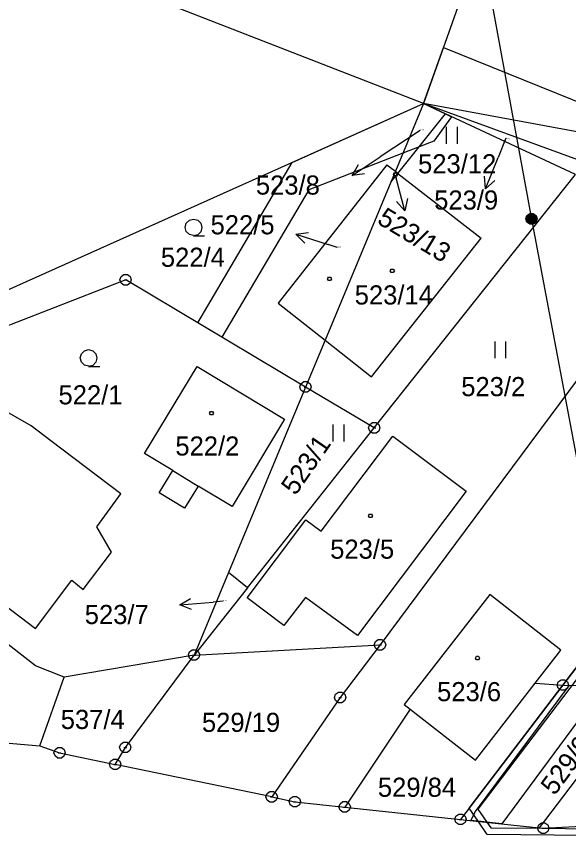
# Model space of a CAD drawing. Extents: x -759060 to -757386, y -1172273 to -1170948.
# Drawn here: x -758613.1 to -758564, y -1171852.3 to -1171779.5 of the extents above; entities that cross this region are included whole.
import ezdxf

# ---------------------------------------------------------------- set-up
doc = ezdxf.new("R2010")
doc.units = 0
for name, color, linetype in [('Vrstva 1', 7, 'Continuous'), ('Vrstva 12', 7, 'Continuous'), ('Vrstva 13', 7, 'Continuous'), ('Vrstva 2', 7, 'Continuous'), ('Vrstva 3', 7, 'Continuous'), ('Vrstva 4', 7, 'Continuous'), ('Vrstva 5', 7, 'Continuous'), ('Vrstva 6', 7, 'Continuous'), ('Vrstva 7', 7, 'Continuous'), ('Vrstva 8', 7, 'Continuous')]:
    doc.layers.add(name, color=color, linetype=linetype)

msp = doc.modelspace()

# ---------------------------------------------------------------- linework, layer by layer
at = {"layer": 'Vrstva 1'}
for p, q in [((-758552.98, -1171720.14), (-758576.87, -1171787.26)), ((-758576.87, -1171787.26), (-758612.62, -1171773.32)), ((-758616.41, -1171804.96), (-758576.87, -1171787.26)), ((-758576.87, -1171787.26), (-758579.37, -1171793.28)), ((-758574.91, -1171788.18), (-758576.87, -1171787.26)), ((-758550.98, -1171792.01), (-758576.87, -1171787.26)), ((-758562.5, -1171792.5), (-758576.87, -1171787.26)), ((-758579.14, -1171793.46), (-758574.91, -1171788.18)), ((-758563.35, -1171793.57), (-758574.91, -1171788.18)), ((-758580.12, -1171792.7), (-758589.8, -1171804.99)), ((-758580.12, -1171792.7), (-758579.37, -1171793.28)), ((-758581.24, -1171816.1), (-758563.35, -1171793.57)), ((-758579.37, -1171793.28), (-758579.77, -1171794.24)), ((-758579.77, -1171794.24), (-758579.14, -1171793.46)), ((-758579.37, -1171793.28), (-758579.14, -1171793.46)), ((-758579.14, -1171793.46), (-758571.73, -1171799.21)), ((-758579.77, -1171794.24), (-758585.61, -1171808.29)), ((-758552.33, -1171797.17), (-758580.73, -1171835.39)), ((-758581.49, -1171811.54), (-758571.73, -1171799.21)), ((-758603.34, -1171802.93), (-758615.26, -1171807.57)), ((-758587.35, -1171812.46), (-758603.34, -1171802.93)), ((-758589.8, -1171804.99), (-758585.61, -1171808.29)), ((-758585.61, -1171808.29), (-758587.35, -1171812.46)), ((-758585.61, -1171808.29), (-758581.49, -1171811.54)), ((-758601.66, -1171818.37), (-758597, -1171810.64)), ((-758597, -1171810.64), (-758589.23, -1171815.31)), ((-758611.74, -1171815.92), (-758617.85, -1171812.39)), ((-758587.35, -1171812.46), (-758594.21, -1171828.95)), ((-758581.24, -1171816.1), (-758587.35, -1171812.46)), ((-758589.23, -1171815.31), (-758593.89, -1171823.07)), ((-758609.99, -1171817.24), (-758611.74, -1171815.92)), ((-758592.51, -1171830.3), (-758581.24, -1171816.1)), ((-758603.77, -1171821.94), (-758609.99, -1171817.24)), ((-758585.97, -1171825.28), (-758579.6, -1171816.83)), ((-758579.6, -1171816.83), (-758573.09, -1171821.73)), ((-758599.16, -1171819.89), (-758601.66, -1171818.37)), ((-758600.35, -1171821.86), (-758599.16, -1171819.89)), ((-758629.53, -1171820.16), (-758611.35, -1171833.94)), ((-758596.9, -1171821.26), (-758598.1, -1171823.23)), ((-758593.89, -1171823.07), (-758596.9, -1171821.26)), ((-758605.91, -1171824.88), (-758603.77, -1171821.94)), ((-758598.1, -1171823.23), (-758600.35, -1171821.86)), ((-758573.09, -1171821.73), (-758582.73, -1171834.56)), ((-758592.53, -1171831.19), (-758587.32, -1171824.27)), ((-758587.32, -1171824.27), (-758585.97, -1171825.28)), ((-758604.59, -1171827.13), (-758605.91, -1171824.88)), ((-758607.12, -1171830.46), (-758604.59, -1171827.13)), ((-758594.21, -1171828.95), (-758597.26, -1171836.29)), ((-758592.51, -1171830.3), (-758594.21, -1171828.95)), ((-758611.37, -1171837.24), (-758620.59, -1171830.09)), ((-758611.35, -1171833.94), (-758608.12, -1171829.64)), ((-758608.12, -1171829.64), (-758607.12, -1171830.46)), ((-758592.51, -1171830.3), (-758597.26, -1171836.29)), ((-758570.98, -1171830.9), (-758578.58, -1171840.69)), ((-758564.65, -1171835.84), (-758570.98, -1171830.9)), ((-758589.27, -1171833.67), (-758592.53, -1171831.19)), ((-758587.35, -1171831.16), (-758589.27, -1171833.67)), ((-758582.73, -1171834.56), (-758587.35, -1171831.16)), ((-758560.74, -1171834.04), (-758564.48, -1171838.96)), ((-758597.26, -1171836.29), (-758580.73, -1171835.39)), ((-758580.73, -1171835.39), (-758584.27, -1171840.06)), ((-758566.95, -1171838.8), (-758564.65, -1171835.84)), ((-758597.26, -1171836.29), (-758608.82, -1171838.24)), ((-758603.37, -1171844.5), (-758597.26, -1171836.29)), ((-758608.82, -1171838.24), (-758611.37, -1171837.24)), ((-758610.96, -1171844.36), (-758608.82, -1171838.24)), ((-758564.48, -1171838.96), (-758573.57, -1171850.9)), ((-758572.24, -1171845.62), (-758566.95, -1171838.8)), ((-758566.95, -1171838.8), (-758564.48, -1171838.96)), ((-758564.48, -1171838.96), (-758557.07, -1171839.12)), ((-758557.07, -1171839.12), (-758566.6, -1171851.65)), ((-758584.27, -1171840.06), (-758590.36, -1171848.9)), ((-758578.05, -1171841.1), (-758583.87, -1171849.8)), ((-758578.58, -1171840.69), (-758578.05, -1171841.1)), ((-758578.05, -1171841.1), (-758572.24, -1171845.62)), ((-758615.05, -1171843.99), (-758610.96, -1171844.36)), ((-758610.96, -1171844.36), (-758609.21, -1171844.98)), ((-758604.27, -1171846.01), (-758603.37, -1171844.5)), ((-758609.21, -1171844.98), (-758604.27, -1171846.01)), ((-758590.36, -1171848.9), (-758604.27, -1171846.01)), ((-758590.36, -1171848.9), (-758588.3, -1171849.33)), ((-758588.3, -1171849.33), (-758583.87, -1171849.8)), ((-758583.87, -1171849.8), (-758573.57, -1171850.9)), ((-758573.57, -1171850.9), (-758566.6, -1171851.65)), ((-758566.22, -1171851.69), (-758558.44, -1171851.28)), ((-758566.6, -1171851.65), (-758566.22, -1171851.69))]:
    msp.add_line(p, q, dxfattribs=at)
at = {"layer": 'Vrstva 12'}
for p, q in [((-758580.12, -1171792.7), (-758589.8, -1171804.99)), ((-758580.12, -1171792.7), (-758579.37, -1171793.28)), ((-758579.37, -1171793.28), (-758579.14, -1171793.46)), ((-758579.14, -1171793.46), (-758571.73, -1171799.21)), ((-758581.49, -1171811.54), (-758571.73, -1171799.21)), ((-758589.8, -1171804.99), (-758585.61, -1171808.29)), ((-758585.61, -1171808.29), (-758581.49, -1171811.54)), ((-758601.66, -1171818.37), (-758597, -1171810.64)), ((-758597, -1171810.64), (-758589.23, -1171815.31)), ((-758589.23, -1171815.31), (-758593.89, -1171823.07)), ((-758585.97, -1171825.28), (-758579.6, -1171816.83)), ((-758579.6, -1171816.83), (-758573.09, -1171821.73)), ((-758599.16, -1171819.89), (-758601.66, -1171818.37)), ((-758599.16, -1171819.89), (-758596.9, -1171821.26)), ((-758593.89, -1171823.07), (-758596.9, -1171821.26)), ((-758573.09, -1171821.73), (-758582.73, -1171834.56)), ((-758592.53, -1171831.19), (-758587.32, -1171824.27)), ((-758587.32, -1171824.27), (-758585.97, -1171825.28)), ((-758570.98, -1171830.9), (-758578.58, -1171840.69)), ((-758564.65, -1171835.84), (-758570.98, -1171830.9)), ((-758589.27, -1171833.67), (-758592.53, -1171831.19)), ((-758587.35, -1171831.16), (-758589.27, -1171833.67)), ((-758582.73, -1171834.56), (-758587.35, -1171831.16)), ((-758566.95, -1171838.8), (-758564.65, -1171835.84)), ((-758572.24, -1171845.62), (-758566.95, -1171838.8)), ((-758578.58, -1171840.69), (-758578.05, -1171841.1)), ((-758578.05, -1171841.1), (-758572.24, -1171845.62))]:
    msp.add_line(p, q, dxfattribs=at)
at = {"layer": 'Vrstva 13'}
for p, q in [((-758576.87, -1171787.26), (-758575.09, -1171782.27)), ((-758575.09, -1171782.27), (-758550.98, -1171792.01)), ((-758588.55, -1171792.49), (-758576.87, -1171787.26)), ((-758576.87, -1171787.26), (-758574.91, -1171788.18)), ((-758550.98, -1171792.01), (-758576.87, -1171787.26)), ((-758574.37, -1171788.43), (-758575.94, -1171790.6)), ((-758574.91, -1171788.18), (-758574.37, -1171788.43)), ((-758575.94, -1171790.6), (-758577.26, -1171791.11)), ((-758578.7, -1171791.67), (-758587.07, -1171794.92)), ((-758577.26, -1171791.11), (-758578.7, -1171791.67)), ((-758596.93, -1171806.75), (-758588.55, -1171792.49)), ((-758587.07, -1171794.92), (-758594.78, -1171808.03)), ((-758532.68, -1171798.24), (-758572.05, -1171849.98)), ((-758594.78, -1171808.03), (-758596.93, -1171806.75)), ((-758564.48, -1171838.96), (-758560.74, -1171834.04)), ((-758572.82, -1171849.91), (-758564.48, -1171838.96)), ((-758572.24, -1171850.2), (-758563.89, -1171838.97)), ((-758562, -1171840.58), (-758569.92, -1171851.29)), ((-758572.02, -1171851.07), (-758572.82, -1171849.91)), ((-758572.05, -1171849.98), (-758571.23, -1171851.15)), ((-758572.66, -1171851), (-758572.24, -1171850.2)), ((-758569.92, -1171851.29), (-758572.66, -1171851)), ((-758571.2, -1171852.25), (-758572.02, -1171851.07)), ((-758572.02, -1171851.07), (-758571.23, -1171851.15)), ((-758571.23, -1171851.15), (-758572.02, -1171851.07)), ((-758571.23, -1171851.15), (-758570.88, -1171851.65)), ((-758570.88, -1171851.65), (-758566.22, -1171851.69)), ((-758566.22, -1171851.69), (-758560.62, -1171851.74)), ((-758560.02, -1171852.34), (-758571.2, -1171852.25))]:
    msp.add_line(p, q, dxfattribs=at)
at = {"layer": 'Vrstva 3'}
for p, q in [((-758574.84, -1171789.33), (-758574.84, -1171790.83)), ((-758573.84, -1171790.83), (-758573.84, -1171789.33)), ((-758570.54, -1171808.4), (-758570.54, -1171809.9)), ((-758569.54, -1171809.9), (-758569.54, -1171808.4)), ((-758584.93, -1171815.79), (-758584.93, -1171817.29)), ((-758583.93, -1171817.29), (-758583.93, -1171815.79))]:
    msp.add_line(p, q, dxfattribs=at)
for points in [[(-758597.3, -1171799), (-758597.68, -1171798.9), (-758597.95, -1171798.63), (-758598.05, -1171798.26), (-758597.95, -1171797.89), (-758597.68, -1171797.62), (-758597.31, -1171797.52), (-758596.94, -1171797.62), (-758596.67, -1171797.89), (-758596.57, -1171798.27), (-758596.67, -1171798.65), (-758596.94, -1171798.92), (-758597.32, -1171799.02), (-758596.32, -1171799.02)], [(-758606.63, -1171810.61), (-758607.01, -1171810.51), (-758607.28, -1171810.24), (-758607.38, -1171809.87), (-758607.28, -1171809.5), (-758607.01, -1171809.23), (-758606.64, -1171809.13), (-758606.27, -1171809.23), (-758606, -1171809.5), (-758605.9, -1171809.88), (-758606, -1171810.26), (-758606.27, -1171810.53), (-758606.65, -1171810.63), (-758605.65, -1171810.63)]]:
    msp.add_lwpolyline(points, dxfattribs=at)
at = {"layer": 'Vrstva 4'}
msp.add_line((-758599.16, -1171819.89), (-758596.9, -1171821.26), dxfattribs=at)
at = {"layer": 'Vrstva 5'}
for points in [[(-758579.27, -1171793.4), (-758579.18, -1171793.55), (-758579.27, -1171793.7), (-758579.45, -1171793.7), (-758579.54, -1171793.55), (-758579.45, -1171793.4)], [(-758579.55, -1171801.98), (-758579.46, -1171802.13), (-758579.55, -1171802.28), (-758579.73, -1171802.28), (-758579.82, -1171802.13), (-758579.73, -1171801.98)], [(-758585.13, -1171802.69), (-758585.04, -1171802.84), (-758585.13, -1171802.99), (-758585.31, -1171802.99), (-758585.4, -1171802.84), (-758585.31, -1171802.69)], [(-758595.61, -1171814.64), (-758595.52, -1171814.79), (-758595.61, -1171814.94), (-758595.79, -1171814.94), (-758595.88, -1171814.79), (-758595.79, -1171814.64)], [(-758581.48, -1171823.77), (-758581.39, -1171823.92), (-758581.48, -1171824.07), (-758581.66, -1171824.07), (-758581.75, -1171823.92), (-758581.66, -1171823.77)], [(-758571.99, -1171836.4), (-758571.9, -1171836.55), (-758571.99, -1171836.7), (-758572.17, -1171836.7), (-758572.26, -1171836.55), (-758572.17, -1171836.4)]]:
    msp.add_lwpolyline(points, close=True, dxfattribs=at)
at = {"layer": 'Vrstva 6'}
for p, q in [((-758585.65, -1171697.17), (-758567.27, -1171797.52)), ((-758567.27, -1171797.52), (-758559.04, -1171841.32))]:
    msp.add_line(p, q, dxfattribs=at)
msp.add_lwpolyline([(-758567.42, -1171797.04), (-758567.11, -1171797.04), (-758566.86, -1171797.22), (-758566.76, -1171797.51), (-758566.86, -1171797.8), (-758567.11, -1171797.98), (-758567.42, -1171797.98), (-758567.67, -1171797.8), (-758567.77, -1171797.51), (-758567.67, -1171797.22), (-758567.42, -1171797.04), (-758567.39, -1171797.08), (-758567.15, -1171797.08), (-758566.99, -1171797.16), (-758567.55, -1171797.16), (-758567.63, -1171797.24), (-758566.91, -1171797.24), (-758566.91, -1171797.32), (-758567.63, -1171797.32), (-758567.67, -1171797.4), (-758566.87, -1171797.4), (-758566.83, -1171797.48), (-758567.71, -1171797.48), (-758567.71, -1171797.56), (-758566.83, -1171797.56), (-758566.86, -1171797.64), (-758567.67, -1171797.64), (-758567.66, -1171797.72), (-758566.85, -1171797.72), (-758566.9, -1171797.8), (-758567.62, -1171797.8), (-758567.54, -1171797.88), (-758566.98, -1171797.88), (-758567.09, -1171797.96), (-758567.43, -1171797.96)], dxfattribs=at)
at = {"layer": 'Vrstva 7'}
for p, q in [((-758577.17, -1171789.64), (-758580.71, -1171791.99)), ((-758569.54, -1171790.32), (-758570.24, -1171792.05)), ((-758583.209, -1171793.65), (-758580.71, -1171791.99)), ((-758571.368, -1171794.83), (-758570.24, -1171792.05)), ((-758579.38, -1171793.58), (-758579.29, -1171793.89)), ((-758578.532, -1171796.793), (-758579.29, -1171793.89)), ((-758588.204, -1171798.877), (-758585.35, -1171799.8)), ((-758584.55, -1171800.06), (-758585.35, -1171799.8)), ((-758598.538, -1171831.834), (-758595.55, -1171831.57)), ((-758594.68, -1171831.49), (-758595.55, -1171831.57))]:
    msp.add_line(p, q, dxfattribs=at)
for points in [[(-758582.099, -1171793.513), (-758583.209, -1171793.65), (-758582.653, -1171792.68)], [(-758570.529, -1171794.091), (-758571.368, -1171794.83), (-758571.456, -1171793.715)], [(-758578.301, -1171795.699), (-758578.532, -1171796.793), (-758579.269, -1171795.951)], [(-758587.407, -1171799.66), (-758588.204, -1171798.877), (-758587.099, -1171798.709)], [(-758597.498, -1171832.244), (-758598.538, -1171831.834), (-758597.586, -1171831.248)]]:
    msp.add_lwpolyline(points, dxfattribs=at)
at = {"layer": 'Vrstva 8'}
for p, q in [((-758603.46, -1171802.93), (-758603.22, -1171802.93)), ((-758587.47, -1171812.46), (-758587.23, -1171812.46)), ((-758581.36, -1171816.1), (-758581.12, -1171816.1)), ((-758580.85, -1171835.39), (-758580.61, -1171835.39)), ((-758597.38, -1171836.29), (-758597.14, -1171836.29)), ((-758564.6, -1171838.96), (-758564.36, -1171838.96)), ((-758584.39, -1171840.06), (-758584.15, -1171840.06)), ((-758603.49, -1171844.5), (-758603.25, -1171844.5)), ((-758609.33, -1171844.98), (-758609.09, -1171844.98)), ((-758604.39, -1171846.01), (-758604.15, -1171846.01)), ((-758590.48, -1171848.9), (-758590.24, -1171848.9)), ((-758588.42, -1171849.33), (-758588.18, -1171849.33)), ((-758583.99, -1171849.8), (-758583.75, -1171849.8)), ((-758573.69, -1171850.9), (-758573.45, -1171850.9)), ((-758566.34, -1171851.69), (-758566.1, -1171851.69))]:
    msp.add_line(p, q, dxfattribs=at)
for points in [[(-758603.19, -1171802.45), (-758602.94, -1171802.63), (-758602.84, -1171802.92), (-758602.94, -1171803.21), (-758603.19, -1171803.39), (-758603.5, -1171803.39), (-758603.75, -1171803.21), (-758603.85, -1171802.92), (-758603.75, -1171802.63), (-758603.5, -1171802.45)], [(-758587.2, -1171811.98), (-758586.95, -1171812.16), (-758586.85, -1171812.45), (-758586.95, -1171812.74), (-758587.2, -1171812.92), (-758587.51, -1171812.92), (-758587.76, -1171812.74), (-758587.86, -1171812.45), (-758587.76, -1171812.16), (-758587.51, -1171811.98)], [(-758581.09, -1171815.62), (-758580.84, -1171815.8), (-758580.74, -1171816.09), (-758580.84, -1171816.38), (-758581.09, -1171816.56), (-758581.4, -1171816.56), (-758581.65, -1171816.38), (-758581.75, -1171816.09), (-758581.65, -1171815.8), (-758581.4, -1171815.62)], [(-758580.58, -1171834.91), (-758580.33, -1171835.09), (-758580.23, -1171835.38), (-758580.33, -1171835.67), (-758580.58, -1171835.85), (-758580.89, -1171835.85), (-758581.14, -1171835.67), (-758581.24, -1171835.38), (-758581.14, -1171835.09), (-758580.89, -1171834.91)], [(-758597.11, -1171835.81), (-758596.86, -1171835.99), (-758596.76, -1171836.28), (-758596.86, -1171836.57), (-758597.11, -1171836.75), (-758597.42, -1171836.75), (-758597.67, -1171836.57), (-758597.77, -1171836.28), (-758597.67, -1171835.99), (-758597.42, -1171835.81)], [(-758564.33, -1171838.48), (-758564.08, -1171838.66), (-758563.98, -1171838.95), (-758564.08, -1171839.24), (-758564.33, -1171839.42), (-758564.64, -1171839.42), (-758564.89, -1171839.24), (-758564.99, -1171838.95), (-758564.89, -1171838.66), (-758564.64, -1171838.48)], [(-758584.12, -1171839.58), (-758583.87, -1171839.76), (-758583.77, -1171840.05), (-758583.87, -1171840.34), (-758584.12, -1171840.52), (-758584.43, -1171840.52), (-758584.68, -1171840.34), (-758584.78, -1171840.05), (-758584.68, -1171839.76), (-758584.43, -1171839.58)], [(-758603.22, -1171844.02), (-758602.97, -1171844.2), (-758602.87, -1171844.49), (-758602.97, -1171844.78), (-758603.22, -1171844.96), (-758603.53, -1171844.96), (-758603.78, -1171844.78), (-758603.88, -1171844.49), (-758603.78, -1171844.2), (-758603.53, -1171844.02)], [(-758609.06, -1171844.5), (-758608.81, -1171844.68), (-758608.71, -1171844.97), (-758608.81, -1171845.26), (-758609.06, -1171845.44), (-758609.37, -1171845.44), (-758609.62, -1171845.26), (-758609.72, -1171844.97), (-758609.62, -1171844.68), (-758609.37, -1171844.5)], [(-758604.12, -1171845.53), (-758603.87, -1171845.71), (-758603.77, -1171846), (-758603.87, -1171846.29), (-758604.12, -1171846.47), (-758604.43, -1171846.47), (-758604.68, -1171846.29), (-758604.78, -1171846), (-758604.68, -1171845.71), (-758604.43, -1171845.53)], [(-758590.21, -1171848.42), (-758589.96, -1171848.6), (-758589.86, -1171848.89), (-758589.96, -1171849.18), (-758590.21, -1171849.36), (-758590.52, -1171849.36), (-758590.77, -1171849.18), (-758590.87, -1171848.89), (-758590.77, -1171848.6), (-758590.52, -1171848.42)], [(-758588.15, -1171848.85), (-758587.9, -1171849.03), (-758587.8, -1171849.32), (-758587.9, -1171849.61), (-758588.15, -1171849.79), (-758588.46, -1171849.79), (-758588.71, -1171849.61), (-758588.81, -1171849.32), (-758588.71, -1171849.03), (-758588.46, -1171848.85)], [(-758583.72, -1171849.32), (-758583.47, -1171849.5), (-758583.37, -1171849.79), (-758583.47, -1171850.08), (-758583.72, -1171850.26), (-758584.03, -1171850.26), (-758584.28, -1171850.08), (-758584.38, -1171849.79), (-758584.28, -1171849.5), (-758584.03, -1171849.32)], [(-758573.42, -1171850.42), (-758573.17, -1171850.6), (-758573.07, -1171850.89), (-758573.17, -1171851.18), (-758573.42, -1171851.36), (-758573.73, -1171851.36), (-758573.98, -1171851.18), (-758574.08, -1171850.89), (-758573.98, -1171850.6), (-758573.73, -1171850.42)], [(-758566.07, -1171851.21), (-758565.82, -1171851.39), (-758565.72, -1171851.68), (-758565.82, -1171851.97), (-758566.07, -1171852.15), (-758566.38, -1171852.15), (-758566.63, -1171851.97), (-758566.73, -1171851.68), (-758566.63, -1171851.39), (-758566.38, -1171851.21)]]:
    msp.add_lwpolyline(points, close=True, dxfattribs=at)

# ---------------------------------------------------------------- texts
at = {"layer": 'Vrstva 2'}
for s, height, p in [('523/8', 0.1, (-758577.156, -1171789.64)), ('523/12', 1.7, (-758577.353, -1171793.46)), ('523/13', 0.1, (-758579.619, -1171793.58)), ('522/4', 1.7, (-758600.213, -1171801.77)), ('522/5', 0.1, (-758584.536, -1171800.06)), ('523/14', 1.7, (-758582.983, -1171805.12)), ('523/2', 1.7, (-758573.513, -1171813.27)), ('522/1', 1.7, (-758609.313, -1171814)), ('522/2', 1.7, (-758598.923, -1171818.55)), ('523/5', 1.7, (-758585.163, -1171827.72)), ('523/7', 0.1, (-758594.666, -1171831.49)), ('523/6', 1.7, (-758575.663, -1171840.39)), ('537/4', 1.7, (-758609.113, -1171842.86)), ('529/19', 1.7, (-758596.563, -1171843.12)), ('529/84', 1.7, (-758580.923, -1171848.89))]:
    msp.add_text(s, height=height, dxfattribs=at).set_placement(p)
for s, height, rotation, p in [('523/9', 0.1, 337.41484, (-758569.527, -1171790.325)), ('523/1', 1.7, 55.40502, (-758588.245, -1171822.175)), ('529/97', 1.7, 53.51426, (-758565.219, -1171848.849))]:
    msp.add_text(s, height=height, rotation=rotation, dxfattribs=at).set_placement(p)
at = {"layer": 'Vrstva 7'}
for s, p in [('523/8', (-758591.77, -1171795.35)), ('523/9', (-758575.919, -1171796.68)), ('522/5', (-758595.796, -1171798.88)), ('523/7', (-758606.979, -1171833.53))]:
    msp.add_text(s, height=1.7, dxfattribs=at).set_placement(p)
msp.add_text('523/13', height=1.7, rotation=328.93507, dxfattribs=at).set_placement((-758581.085, -1171797.86))

doc.saveas('drawing.dxf')
